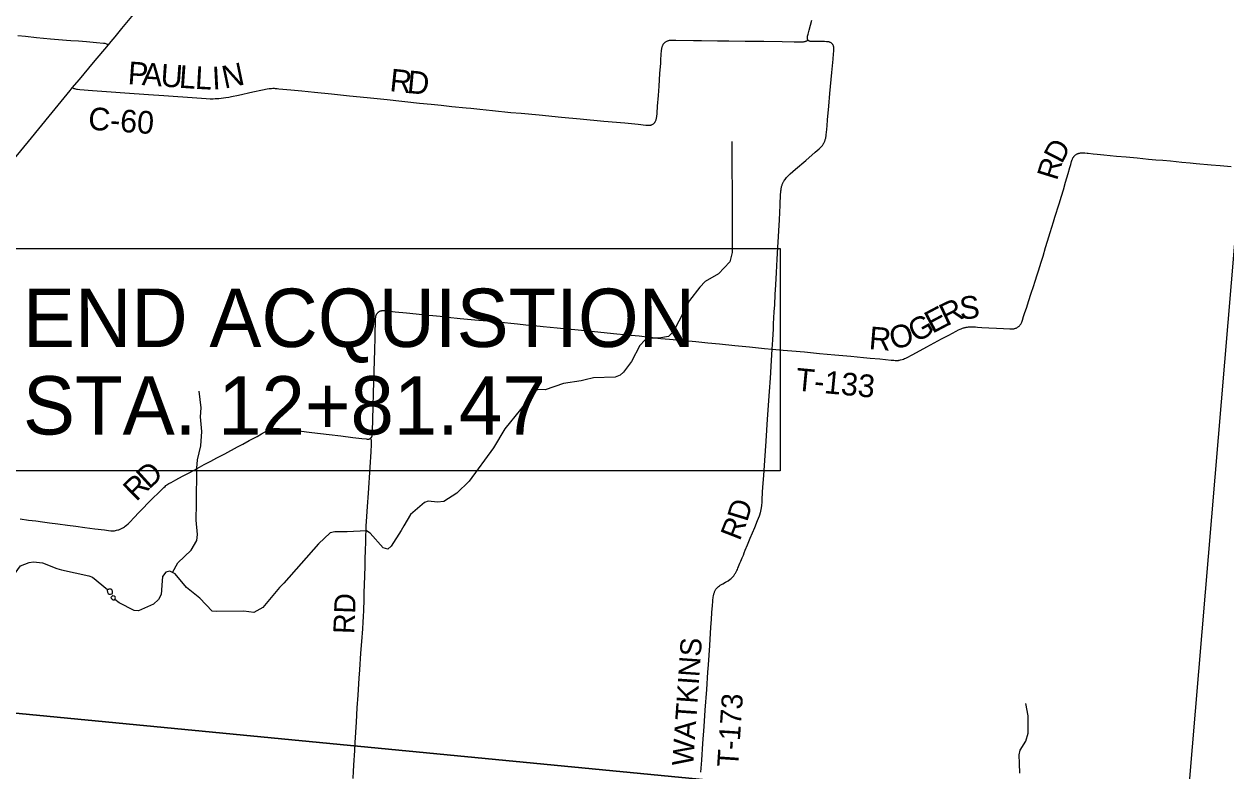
# Model space of a CAD drawing. Extents: x -13.9 to 69.1, y -25.2 to 26.1.
# Drawn here: x 5.08 to 7.963, y 18.591 to 20.383 of the extents above; entities that cross this region are included whole.
import ezdxf

# ---------------------------------------------------------------- set-up
doc = ezdxf.new("R2010")
doc.units = 0
for name, color, linetype in [('GM_X_County_Road', 7, 'Continuous'), ('GM_X_County_Road_Text', 7, 'Continuous'), ('GM_X_Major_River', 7, 'Continuous'), ('GM_X_Minor_Lake', 7, 'Continuous'), ('GM_X_Minor_River', 7, 'Continuous'), ('GM_X_Township', 7, 'Continuous'), ('GM_X_Township_Road', 7, 'Continuous'), ('GM_X_Township_Road_Text', 7, 'Continuous'), ('SH_Text', 7, 'Continuous')]:
    doc.layers.add(name, color=color, linetype=linetype)

msp = doc.modelspace()

# ---------------------------------------------------------------- linework, layer by layer
at = {"layer": 'GM_X_County_Road'}
for points in [[(5.2823, 20.3338), (5.2888, 20.3416), (5.298, 20.3527), (5.314, 20.3724), (5.3499, 20.416)], [(5.1953, 20.2303), (5.1978, 20.2294), (5.1993, 20.2289), (5.2009, 20.2285), (5.203, 20.2279), (5.2053, 20.2275), (5.208, 20.2271), (5.2135, 20.2265), (5.2438, 20.2242), (5.289, 20.221), (5.321, 20.2184), (5.3784, 20.2142), (5.4153, 20.2117), (5.4937, 20.2062), (5.5163, 20.2047), (5.5262, 20.2043), (5.5299, 20.2043), (5.5334, 20.2043), (5.5379, 20.2045), (5.5423, 20.2048), (5.5467, 20.2051), (5.5522, 20.2056), (5.5578, 20.2063), (5.5637, 20.2072), (5.5705, 20.2084), (5.5773, 20.2097), (5.5941, 20.2132), (5.6288, 20.2208), (5.6516, 20.2256), (5.6628, 20.2278), (5.6674, 20.2286), (5.6703, 20.2289), (5.6732, 20.2291), (5.6764, 20.2293), (5.6793, 20.2293), (5.6823, 20.2291), (5.6868, 20.2288), (5.6911, 20.2284), (5.7197, 20.2257), (5.7456, 20.2231), (5.7764, 20.2199), (5.8171, 20.2157), (5.8606, 20.2114), (5.903, 20.207), (5.9504, 20.2023), (6.0285, 20.1938), (6.0565, 20.1909), (6.0802, 20.1886), (6.1055, 20.1859), (6.1402, 20.1824), (6.1517, 20.1813), (6.1732, 20.1792), (6.2035, 20.176), (6.2476, 20.1716), (6.2717, 20.1694), (6.3153, 20.1654), (6.3687, 20.1603), (6.4138, 20.1558), (6.47, 20.1508), (6.5207, 20.1461), (6.5526, 20.1429), (6.5708, 20.1411), (6.5758, 20.1407), (6.5774, 20.1407), (6.5791, 20.1407), (6.5806, 20.1408), (6.5818, 20.141), (6.5829, 20.1412), (6.5841, 20.1415), (6.5852, 20.1419), (6.5866, 20.1424), (6.5876, 20.143), (6.5891, 20.1439), (6.5903, 20.1449), (6.5915, 20.1461), (6.5923, 20.147), (6.5928, 20.1477), (6.5936, 20.1489), (6.5944, 20.1504), (6.5952, 20.1522), (6.5957, 20.1537), (6.5962, 20.1553), (6.5966, 20.1571), (6.597, 20.1591), (6.5973, 20.1612), (6.598, 20.1696), (6.5992, 20.1868), (6.6011, 20.2123), (6.6027, 20.2342), (6.6049, 20.265), (6.6068, 20.2899), (6.6074, 20.2988), (6.6081, 20.3089), (6.6082, 20.3125), (6.6086, 20.3173), (6.6089, 20.3203), (6.609, 20.3215), (6.6092, 20.3228), (6.6095, 20.3243), (6.6098, 20.3262), (6.6102, 20.3278), (6.6105, 20.329), (6.6109, 20.3302), (6.6114, 20.3315), (6.6118, 20.3326), (6.6124, 20.3337), (6.613, 20.3349), (6.6138, 20.336), (6.6146, 20.3371), (6.6155, 20.3381), (6.6167, 20.3393), (6.6177, 20.3402), (6.6188, 20.341), (6.6199, 20.3417), (6.6213, 20.3424), (6.6227, 20.343), (6.6237, 20.3434), (6.6251, 20.3438), (6.6264, 20.3442), (6.6279, 20.3444), (6.6293, 20.3446), (6.6311, 20.3448), (6.6333, 20.3448), (6.6432, 20.3447), (6.6852, 20.3437), (6.7045, 20.3436), (6.7432, 20.3432), (6.7703, 20.343), (6.809, 20.3427), (6.8538, 20.3422), (6.898, 20.3416), (6.9268, 20.3411), (6.9422, 20.3409), (6.9478, 20.341), (6.9494, 20.3411), (6.9511, 20.3413), (6.9522, 20.3415), (6.9532, 20.3418), (6.9543, 20.3421), (6.9554, 20.3425), (6.9564, 20.343), (6.9576, 20.3435), (6.9589, 20.3442), (6.9601, 20.3448)], [(5.1953, 20.2303), (5.2124, 20.2508), (5.2465, 20.2914), (5.2823, 20.3338)], [(5.0423, 20.0435), (5.0901, 20.1019), (5.1471, 20.1716), (5.1902, 20.2242), (5.1953, 20.2303)], [(5.9109, 19.3896), (5.9114, 19.39), (5.9119, 19.3905), (5.9126, 19.3912), (5.9131, 19.3919), (5.9135, 19.3926), (5.9139, 19.3932), (5.9141, 19.3939), (5.9143, 19.3948), (5.9145, 19.3955), (5.9148, 19.3986), (5.9151, 19.407), (5.9161, 19.4349), (5.9171, 19.4658), (5.918, 19.4979), (5.9194, 19.5496), (5.9207, 19.6014), (5.9216, 19.6305), (5.9221, 19.6495), (5.9224, 19.662), (5.9226, 19.6721), (5.9227, 19.6752), (5.9229, 19.6776), (5.9232, 19.6797), (5.9235, 19.6815), (5.9238, 19.683), (5.9242, 19.6842), (5.9245, 19.6852), (5.9248, 19.6862), (5.9253, 19.6872), (5.9259, 19.6882), (5.9265, 19.6891), (5.9271, 19.69), (5.928, 19.691), (5.9288, 19.6918), (5.9297, 19.6925), (5.9306, 19.6932), (5.9315, 19.6938), (5.9323, 19.6943), (5.9334, 19.6948), (5.9344, 19.6952), (5.9357, 19.6955), (5.937, 19.6957), (5.9381, 19.6959), (5.9394, 19.696), (5.9409, 19.696), (5.9427, 19.696), (5.9445, 19.6959), (5.9482, 19.6955), (5.957, 19.6946), (5.9698, 19.6933), (5.9972, 19.6906), (6.0204, 19.6883), (6.0418, 19.6859), (6.06, 19.684), (6.0776, 19.6822), (6.0963, 19.6802), (6.126, 19.6772), (6.1611, 19.6739), (6.1903, 19.6711), (6.2164, 19.6686), (6.2632, 19.664), (6.2836, 19.6618), (6.3021, 19.6599), (6.3246, 19.6577), (6.3582, 19.6544), (6.383, 19.6519), (6.4011, 19.6502), (6.4248, 19.6479), (6.4559, 19.6449), (6.4935, 19.6413), (6.5261, 19.6381), (6.5549, 19.6352), (6.5803, 19.6319), (6.5869, 19.6311), (6.593, 19.6304), (6.6072, 19.6291), (6.6279, 19.6273), (6.6907, 19.6217), (6.7199, 19.6189), (6.7479, 19.6161), (6.7848, 19.6124), (6.8198, 19.6087), (6.8555, 19.6049), (6.8745, 19.6033)], [(5.0705, 19.196), (5.0906, 19.1935), (5.1075, 19.1912), (5.1236, 19.189), (5.1407, 19.1866), (5.1603, 19.1841), (5.184, 19.181), (5.2041, 19.1784), (5.2254, 19.1756), (5.2495, 19.1725), (5.2728, 19.1697), (5.2822, 19.1685), (5.2877, 19.1678), (5.2918, 19.1676), (5.2945, 19.1677), (5.2967, 19.1679), (5.2991, 19.1683), (5.3013, 19.1688), (5.3048, 19.1697), (5.3068, 19.1702), (5.3088, 19.1708), (5.3103, 19.1714), (5.3116, 19.172), (5.3135, 19.1729), (5.3151, 19.1738), (5.3167, 19.1747), (5.3185, 19.1758), (5.3202, 19.177), (5.3222, 19.1784), (5.3253, 19.1809), (5.3295, 19.1847), (5.3324, 19.1875), (5.3445, 19.2003), (5.3544, 19.211), (5.365, 19.222), (5.3766, 19.2337), (5.3885, 19.2456), (5.402, 19.2591), (5.41, 19.2668), (5.4146, 19.2712), (5.4178, 19.274), (5.4201, 19.276), (5.4212, 19.2769), (5.4225, 19.2779), (5.4249, 19.2796), (5.4272, 19.281), (5.4322, 19.2838), (5.4378, 19.2868), (5.4438, 19.29), (5.46, 19.2985), (5.4773, 19.3077), (5.4951, 19.3173), (5.5119, 19.3264), (5.5277, 19.3348), (5.5421, 19.3423), (5.5611, 19.3525), (5.5913, 19.3688), (5.6041, 19.3756), (5.6198, 19.3841), (5.6385, 19.3942), (5.6489, 19.3999), (5.6622, 19.4071), (5.6647, 19.4083), (5.6673, 19.4095), (5.6698, 19.4104), (5.6722, 19.4113), (5.6744, 19.4119), (5.6755, 19.4121), (5.6764, 19.4123), (5.6785, 19.4127), (5.6808, 19.4129), (5.6828, 19.4131), (5.6846, 19.4131), (5.6862, 19.4131), (5.6892, 19.4129), (5.6917, 19.4128), (5.6938, 19.4126), (5.6984, 19.4122), (5.7215, 19.4095), (5.7387, 19.4076), (5.7699, 19.4037), (5.8116, 19.3985), (5.8396, 19.3951), (5.8682, 19.3917), (5.8896, 19.389), (5.9, 19.388), (5.9024, 19.3878), (5.9043, 19.3876), (5.9061, 19.3876), (5.907, 19.3877), (5.9079, 19.3879), (5.9087, 19.3882), (5.9094, 19.3885), (5.9101, 19.389), (5.9109, 19.3896)]]:
    msp.add_lwpolyline(points, dxfattribs=at)
at = {"layer": 'GM_X_Major_River'}
for points in [[(6.7772, 20.1019), (6.7785, 19.9194), (6.7783, 19.8354), (6.7728, 19.813), (6.7457, 19.7842), (6.7137, 19.766), (6.7007, 19.7524), (6.6759, 19.7203), (6.6378, 19.6459), (6.6255, 19.6338), (6.6025, 19.6299), (6.581, 19.63), (6.5687, 19.6252), (6.5571, 19.6124), (6.5368, 19.5739), (6.5178, 19.5485), (6.5093, 19.5407), (6.4978, 19.5359), (6.4459, 19.5345), (6.4253, 19.5298), (6.4161, 19.5271), (6.3733, 19.5208), (6.3299, 19.5057), (6.3118, 19.5065), (6.3019, 19.5002), (6.2708, 19.459), (6.2326, 19.4123), (6.2058, 19.3663), (6.1471, 19.2865), (6.118, 19.2577), (6.0863, 19.238), (6.0711, 19.2362), (6.049, 19.2385), (6.0398, 19.2358), (6.007, 19.2067), (5.991, 19.1794), (5.984, 19.1683), (5.9605, 19.131), (5.9519, 19.1239), (5.9409, 19.1271), (5.9095, 19.1619), (5.9009, 19.1672), (5.8547, 19.1649), (5.8255, 19.1652), (5.8136, 19.1626), (5.7862, 19.1366), (5.7027, 19.0418), (5.6927, 19.0318), (5.6521, 18.9832), (5.6307, 18.9714), (5.6069, 18.9748), (5.5409, 18.974), (5.5305, 18.975), (5.5014, 19.0058), (5.4692, 19.0319), (5.4419, 19.0642), (5.4296, 19.071), (5.4194, 19.0683), (5.4118, 19.0579), (5.4098, 19.0372), (5.4095, 19.0249), (5.4083, 19.0144), (5.4021, 19.0025), (5.3901, 18.9919), (5.3544, 18.9756), (5.344, 18.9765), (5.3077, 18.9951), (5.2975, 19.0031)], [(4.8397, 18.6945), (4.8672, 18.7259), (4.9208, 18.8058), (4.9317, 18.8321), (4.9358, 18.8538), (4.9422, 18.8675), (4.943, 18.8776), (4.9565, 18.917), (4.9627, 18.975), (4.9726, 19.0006), (4.9871, 19.0239), (5.0063, 19.0406), (5.0165, 19.0476), (5.0544, 19.0602), (5.0714, 19.0839), (5.0917, 19.0918), (5.1025, 19.0934), (5.124, 19.0911), (5.1581, 19.0773), (5.1695, 19.0737), (5.2352, 19.0599), (5.2439, 19.0561), (5.28, 19.027)], [(5.28, 19.027), (5.2793, 19.0242), (5.2799, 19.0204), (5.2818, 19.0175), (5.2842, 19.0153), (5.2872, 19.0152), (5.2906, 19.0166), (5.292, 19.0191), (5.2917, 19.0224), (5.2904, 19.026), (5.2878, 19.0273), (5.2857, 19.0279), (5.2834, 19.028), (5.2827, 19.0276)], [(5.28, 19.027), (5.2827, 19.0276)], [(5.2877, 19.0075), (5.2887, 19.0061), (5.2907, 19.0035), (5.293, 19.002), (5.295, 19.0016), (5.2967, 19.0023), (5.2977, 19.0033), (5.2988, 19.0066), (5.2982, 19.0091), (5.2955, 19.0106), (5.2928, 19.0118), (5.2915, 19.0115)], [(5.2915, 19.0115), (5.2877, 19.0075)]]:
    msp.add_lwpolyline(points, dxfattribs=at)
at = {"layer": 'GM_X_Minor_Lake'}
msp.add_lwpolyline([(4.8397, 18.6945), (4.8672, 18.7259), (4.9208, 18.8058), (4.9317, 18.8321), (4.9358, 18.8538), (4.9422, 18.8675), (4.943, 18.8776), (4.9565, 18.917), (4.9627, 18.975), (4.9726, 19.0006), (4.9871, 19.0239), (5.0063, 19.0406), (5.0165, 19.0476), (5.0544, 19.0602), (5.0714, 19.0839), (5.0917, 19.0918), (5.1025, 19.0934), (5.124, 19.0911), (5.1581, 19.0773), (5.1695, 19.0737), (5.2352, 19.0599), (5.2439, 19.0561), (5.28, 19.027)], dxfattribs=at)
at = {"layer": 'GM_X_Minor_River'}
for points in [[(5.4361, 19.0674), (5.4486, 19.0909), (5.4804, 19.1212), (5.4943, 19.1442), (5.4959, 19.1587), (5.4924, 19.1933), (5.4931, 19.2333), (5.4938, 19.3177), (5.4958, 19.338), (5.5038, 19.3713), (5.5064, 19.4055), (5.5029, 19.4412), (5.5043, 19.4626), (5.4995, 19.5024)], [(7.4684, 18.5864), (7.4671, 18.609), (7.4664, 18.6301), (7.4693, 18.6416), (7.4828, 18.6625), (7.4885, 18.682), (7.4886, 18.7238), (7.4823, 18.7534)]]:
    msp.add_lwpolyline(points, dxfattribs=at)
at = {"layer": 'GM_X_Township'}
msp.add_lwpolyline([(8.0976, 21.2145), (2.668, 21.2145), (2.5713, 21.1249), (2.5376, 21.0933), (2.5207, 21.0774), (2.9282, 20.5283), (2.3149, 19.9943), (2.3345, 19.9924), (2.4186, 19.989), (2.4692, 19.987), (2.5176, 19.987), (2.5995, 20.0118), (2.5714, 18.9023), (4.5288, 18.7816), (7.8661, 18.459), (7.9988, 20.0382), (8.0428, 20.5625)], close=True, dxfattribs=at)
msp.add_lwpolyline([(7.5668, 14.8972), (7.5796, 15.0495), (7.6196, 15.5251), (7.6913, 16.3786), (7.7402, 16.961), (7.7786, 17.4181), (7.8394, 18.1408), (7.8661, 18.459), (4.5288, 18.7816)], dxfattribs=at)
at = {"layer": 'GM_X_Township_Road'}
for points in [[(6.9601, 20.3448), (6.9596, 20.3456), (6.9592, 20.3464), (6.9589, 20.3472), (6.9588, 20.3481), (6.9586, 20.3489), (6.9586, 20.3502), (6.9586, 20.3513), (6.9587, 20.3522), (6.9588, 20.3533), (6.9589, 20.3542), (6.9601, 20.3594), (6.9627, 20.3691), (6.9695, 20.3924)], [(5.0647, 20.356), (5.0832, 20.354), (5.1098, 20.3514), (5.1432, 20.3483), (5.1624, 20.3467), (5.1816, 20.345), (5.1915, 20.3442), (5.2105, 20.3428), (5.2298, 20.3414), (5.2531, 20.3393), (5.2699, 20.3376), (5.272, 20.3374), (5.2737, 20.3372), (5.2756, 20.3367), (5.2769, 20.3363), (5.2796, 20.3352), (5.2823, 20.3338)], [(6.8745, 19.6033), (6.8758, 19.6257), (6.8771, 19.6523), (6.8777, 19.6642), (6.8792, 19.6933), (6.8802, 19.7099), (6.8817, 19.7348), (6.8828, 19.758), (6.8846, 19.7877), (6.8864, 19.8197), (6.8879, 19.847), (6.8916, 19.9135), (6.8934, 19.9485), (6.8945, 19.9753), (6.8948, 19.9794), (6.8952, 19.9832), (6.8955, 19.9859), (6.8958, 19.9883), (6.896, 19.9898), (6.8962, 19.9909), (6.8965, 19.9923), (6.8968, 19.9937), (6.8972, 19.9952), (6.8978, 19.9972), (6.8983, 19.9986), (6.8988, 19.9999), (6.8994, 20.0015), (6.9, 20.0027), (6.9005, 20.0038), (6.9011, 20.0049), (6.9018, 20.0062), (6.9027, 20.0075), (6.9039, 20.0093), (6.905, 20.0108), (6.9082, 20.0149), (6.9125, 20.0195), (6.9175, 20.0242), (6.9239, 20.0299), (6.93, 20.0351), (6.9547, 20.0561), (6.9776, 20.0757), (6.9872, 20.0842), (6.9902, 20.0871), (6.9917, 20.0887), (6.9928, 20.0899), (6.9938, 20.0911), (6.9948, 20.0924), (6.9958, 20.0938), (6.9967, 20.0952), (6.9973, 20.0964), (6.9982, 20.0981), (6.9991, 20.0996), (6.9998, 20.1012), (7.0003, 20.1024), (7.0006, 20.1034), (7.0011, 20.1048), (7.0016, 20.1062), (7.0022, 20.1081), (7.0026, 20.1097), (7.0029, 20.1113), (7.0032, 20.1131), (7.0035, 20.1148), (7.004, 20.1185), (7.0045, 20.1231), (7.006, 20.1391), (7.0072, 20.1533), (7.0099, 20.1865), (7.0127, 20.2167), (7.0172, 20.267), (7.0203, 20.2989), (7.0215, 20.3119), (7.0221, 20.318), (7.0224, 20.3222), (7.0224, 20.3235), (7.0224, 20.3247), (7.0223, 20.3258), (7.0222, 20.3268), (7.0219, 20.3285), (7.0216, 20.3296), (7.0213, 20.3306), (7.021, 20.3315), (7.0206, 20.3324), (7.0199, 20.3336), (7.0193, 20.3344), (7.0188, 20.3352), (7.0182, 20.3359), (7.0175, 20.3365), (7.0163, 20.3375), (7.0153, 20.3382), (7.0143, 20.3389), (7.0134, 20.3394), (7.0121, 20.34), (7.0113, 20.3403), (7.0104, 20.3406), (7.0095, 20.3408), (7.0087, 20.3409), (7.0071, 20.3411), (7.0042, 20.3411), (6.9993, 20.3412), (6.9876, 20.3413), (6.9776, 20.3412), (6.9713, 20.3413), (6.9679, 20.3414), (6.9665, 20.3416), (6.9652, 20.3418), (6.9642, 20.342), (6.9635, 20.3422), (6.9626, 20.3426), (6.9619, 20.343), (6.9612, 20.3436), (6.9606, 20.3441), (6.9601, 20.3448)], [(6.8745, 19.6033), (6.9004, 19.6013), (6.9212, 19.5994), (6.9517, 19.5967), (6.9874, 19.5933), (7.0246, 19.59), (7.0626, 19.5865), (7.0933, 19.5836), (7.1091, 19.5821), (7.1328, 19.5799), (7.146, 19.5786), (7.1599, 19.5773), (7.1661, 19.5768), (7.1694, 19.5766), (7.1721, 19.5765), (7.1747, 19.5765), (7.1759, 19.5765), (7.1768, 19.5766), (7.1778, 19.5767), (7.1786, 19.5768), (7.1799, 19.5771), (7.1819, 19.5775), (7.186, 19.5787), (7.1888, 19.5796), (7.1918, 19.5808), (7.1946, 19.5821), (7.1978, 19.5837), (7.2097, 19.59), (7.2207, 19.5956), (7.2455, 19.6088), (7.2805, 19.6278), (7.2983, 19.6373), (7.3157, 19.6466), (7.3212, 19.6494), (7.3249, 19.6511), (7.3278, 19.6524), (7.3292, 19.653), (7.3308, 19.6536), (7.3328, 19.6543), (7.3349, 19.6549), (7.3363, 19.6553), (7.3381, 19.6557), (7.3398, 19.6561), (7.3413, 19.6563), (7.3427, 19.6565), (7.3449, 19.6566), (7.3476, 19.6568), (7.3519, 19.6569), (7.3566, 19.6569), (7.3615, 19.6566), (7.3669, 19.6563), (7.3767, 19.6557), (7.3938, 19.6548), (7.412, 19.654), (7.4287, 19.6531), (7.4445, 19.6523), (7.4501, 19.6522), (7.4513, 19.6522), (7.4525, 19.6523), (7.4538, 19.6525), (7.4555, 19.6528), (7.4566, 19.6531), (7.4577, 19.6534), (7.4592, 19.654), (7.4607, 19.6546), (7.4619, 19.6552), (7.4629, 19.6559), (7.4641, 19.6567), (7.4654, 19.6577), (7.4663, 19.6586), (7.4673, 19.6597), (7.4686, 19.6611), (7.4696, 19.6624), (7.4703, 19.6635), (7.4711, 19.6649), (7.472, 19.6665), (7.4727, 19.6682), (7.4736, 19.6705), (7.4746, 19.673), (7.4773, 19.6815), (7.4797, 19.689), (7.4848, 19.7044), (7.4891, 19.7176), (7.4958, 19.738), (7.501, 19.7539), (7.5051, 19.7664), (7.5101, 19.7819), (7.513, 19.7911), (7.5194, 19.812), (7.5239, 19.8269), (7.5301, 19.8474), (7.5347, 19.8627), (7.541, 19.8835), (7.5487, 19.9092), (7.5523, 19.9204), (7.5624, 19.9523), (7.568, 19.9702), (7.5727, 19.9857), (7.578, 20.0037), (7.584, 20.0249), (7.5882, 20.0394), (7.5903, 20.0465), (7.5925, 20.0538), (7.5939, 20.0584), (7.5942, 20.0593), (7.5946, 20.0602), (7.5952, 20.0614), (7.5957, 20.0624), (7.5962, 20.0632), (7.5968, 20.0642), (7.5974, 20.065), (7.598, 20.0659), (7.5986, 20.0666), (7.5994, 20.0674), (7.6002, 20.0682), (7.6011, 20.069), (7.6021, 20.0698), (7.6034, 20.0706), (7.6045, 20.0712), (7.6056, 20.0718), (7.6066, 20.0723), (7.6076, 20.0727), (7.6087, 20.0731), (7.6098, 20.0734), (7.6111, 20.0737), (7.6124, 20.074), (7.6136, 20.0742), (7.6147, 20.0742), (7.616, 20.0743), (7.6177, 20.0743), (7.6195, 20.0743), (7.6239, 20.0741), (7.6294, 20.0737), (7.6322, 20.0734), (7.6441, 20.0722), (7.6536, 20.0711), (7.6701, 20.0694), (7.685, 20.068), (7.6998, 20.0666), (7.7229, 20.0646), (7.7493, 20.0621), (7.7768, 20.0596), (7.7944, 20.058), (7.8115, 20.0565), (7.8296, 20.0549), (7.8566, 20.0524), (7.8764, 20.0505), (7.8912, 20.049), (7.9268, 20.0458), (7.9489, 20.0437), (7.9748, 20.0413)], [(6.7032, 18.5885), (6.7051, 18.617), (6.708, 18.6573), (6.7109, 18.6982), (6.7138, 18.7373), (6.7173, 18.7872), (6.7201, 18.8281), (6.7213, 18.8459), (6.7244, 18.8927), (6.7272, 18.936), (6.7285, 18.9544), (6.7297, 18.9716), (6.7307, 18.9883), (6.7315, 18.9981), (6.7319, 19.0028), (6.7324, 19.0059), (6.7328, 19.0086), (6.7332, 19.0112), (6.7337, 19.0132), (6.734, 19.0147), (6.7346, 19.0165), (6.7351, 19.0183), (6.7357, 19.0198), (6.7362, 19.0215), (6.7368, 19.0229), (6.7376, 19.0244), (6.7384, 19.026), (6.7392, 19.0272), (6.7401, 19.0283), (6.7414, 19.0298), (6.7427, 19.0312), (6.7441, 19.0327), (6.7458, 19.0342), (6.7476, 19.0357), (6.7491, 19.0368), (6.7511, 19.0381), (6.7555, 19.0406), (6.7619, 19.044), (6.7683, 19.0477), (6.7733, 19.0513), (6.776, 19.0534), (6.7776, 19.055), (6.7791, 19.0566), (6.7806, 19.0583), (6.7818, 19.0598), (6.7829, 19.0613), (6.784, 19.0629), (6.7849, 19.0643), (6.786, 19.0661), (6.787, 19.0677), (6.7877, 19.0691), (6.7887, 19.0708), (6.7896, 19.0727), (6.7906, 19.0749), (6.7921, 19.0782), (6.7936, 19.0818), (6.7968, 19.09), (6.7989, 19.0949), (6.8022, 19.1031), (6.805, 19.1095), (6.8072, 19.115), (6.8097, 19.1209), (6.8151, 19.134), (6.8216, 19.1498), (6.8323, 19.1752), (6.8391, 19.1922), (6.8414, 19.1982), (6.8435, 19.2037), (6.845, 19.2082), (6.8455, 19.2097), (6.8458, 19.211), (6.8462, 19.2123), (6.8466, 19.2136), (6.8469, 19.2148), (6.8472, 19.2161), (6.8476, 19.2182), (6.848, 19.2201), (6.8484, 19.2222), (6.8486, 19.2238), (6.8488, 19.2253), (6.849, 19.2266), (6.8493, 19.2297), (6.8498, 19.2349), (6.8504, 19.242), (6.8513, 19.26), (6.8521, 19.2723), (6.8539, 19.3005), (6.8562, 19.3364), (6.8594, 19.3826), (6.8631, 19.4354), (6.8679, 19.5018), (6.87, 19.5339), (6.8728, 19.5766), (6.8745, 19.6033)], [(5.8736, 18.6557), (5.8738, 18.6594), (5.8769, 18.7086), (5.8789, 18.7425), (5.8808, 18.7733), (5.8835, 18.8137), (5.8849, 18.8344), (5.8878, 18.8742), (5.8897, 18.9018), (5.8919, 18.9323), (5.893, 18.9487), (5.8936, 18.9619), (5.8943, 18.9762), (5.8952, 19.0029), (5.8957, 19.0195), (5.8962, 19.038), (5.8975, 19.0819), (5.8982, 19.1027), (5.8988, 19.1182), (5.8993, 19.1437), (5.8997, 19.1556), (5.9002, 19.1681), (5.9006, 19.1795), (5.9012, 19.1899), (5.9035, 19.2263), (5.9055, 19.2583), (5.9096, 19.3206), (5.912, 19.3568), (5.9132, 19.3746), (5.9134, 19.3803), (5.9134, 19.3816), (5.9134, 19.3825), (5.9133, 19.3832), (5.9132, 19.384), (5.913, 19.3847), (5.912, 19.3869), (5.9109, 19.3896)], [(5.8689, 18.5735), (5.8699, 18.5906), (5.8713, 18.6179), (5.8719, 18.628), (5.8736, 18.6557)]]:
    msp.add_lwpolyline(points, dxfattribs=at)
at = {"layer": 'SH_Text'}
msp.add_lwpolyline([(5.0073, 19.8447), (6.8934, 19.8447), (6.8934, 19.3117), (5.0073, 19.3117)], close=True, dxfattribs=at)

# ---------------------------------------------------------------- texts
at = {"layer": 'GM_X_County_Road_Text'}
for s, height, rotation, p in [('P', 0.0544, 355.9286, (5.3273, 20.2396)), ('A', 0.0544, 355.9258, (5.3614, 20.2371)), ('U', 0.0544, 355.9285, (5.4058, 20.234)), ('L', 0.0544, 355.9647, (5.4502, 20.2308)), ('L', 0.0544, 356.9337, (5.4888, 20.2281)), ('I', 0.0544, 2.9393, (5.5319, 20.2261)), ('N', 0.0542, 11.8183, (5.5605, 20.2282)), ('R', 0.0543, 353.9843, (5.9551, 20.2227)), ('D', 0.0544, 354.5055, (5.9969, 20.2183)), ('C-60', 0.05437, 355.9447, (5.2322, 20.1303)), ('D', 0.0528, 42.2654, (5.3792, 19.2659)), ('R', 0.0527, 44.4558, (5.3489, 19.2361))]:
    msp.add_text(s, height=height, rotation=rotation, dxfattribs=at).set_placement(p)
at = {"layer": 'GM_X_Township_Road_Text'}
for s, height, rotation, p in [('D', 0.0515, 62.7161, (7.5691, 20.0463)), ('R', 0.0509, 72.942, (7.5571, 20.0063)), ('R', 0.0538, 25.4619, (7.2919, 19.6576)), ('S', 0.0544, 4.7625, (7.3255, 19.6745)), ('E', 0.0537, 27.8682, (7.2584, 19.6399)), ('O', 0.0542, 14.0712, (7.163, 19.6018)), ('G', 0.0536, 29.3277, (7.2193, 19.6179)), ('R', 0.0544, 355.3567, (7.1049, 19.6038)), ('T-133', 0.05435, 354.5767, (6.9289, 19.5045)), ('D', 0.0509, 73.1314, (6.814, 19.1874)), ('R', 0.0511, 68.7031, (6.7963, 19.1418)), ('RD', 0.05055, 87.8196, (5.8718, 18.9194)), ('WATKINS', 0.05057, 86.004, (6.6844, 18.6022)), ('T-173', 0.05057, 86.1287, (6.7924, 18.5993))]:
    msp.add_text(s, height=height, rotation=rotation, dxfattribs=at).set_placement(p)
at = {"layer": 'SH_Text'}
for s, p in [('END ACQUISTION', (5.0769, 19.6086)), ('STA. 12+81.47', (5.0769, 19.3986))]:
    msp.add_text(s, height=0.14, dxfattribs=at).set_placement(p)

doc.saveas('drawing.dxf')
